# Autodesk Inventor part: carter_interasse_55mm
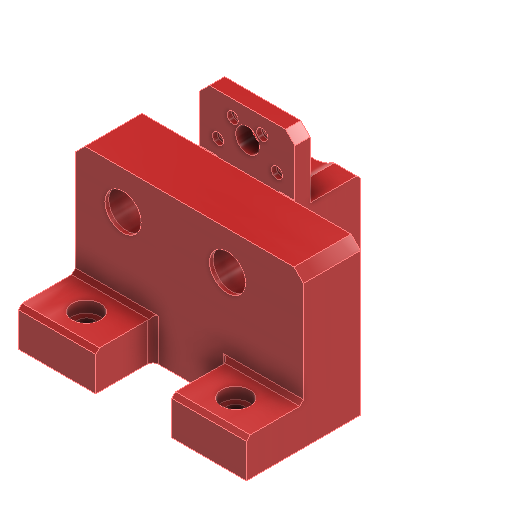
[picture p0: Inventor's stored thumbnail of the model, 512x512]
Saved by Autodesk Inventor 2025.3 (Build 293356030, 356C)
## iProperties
Created: 2026-09
Part Number: carter_interasse_55mm
Material: Plastica PET
Document SubType Name: Modeling
Designer: R5800u
Density: 1.541 g/cm^3
Appearance: Rosso
Author: R5800u
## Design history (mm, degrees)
sketch "Schizzo1"
  geometry: L1 (-75, 20)-(45, 20); L2 (45, 20)-(45, -40); L3 (45, -40)-(-75, -40); L4 (-75, -40)-(-75, 20); C1 r 11 at (5, 0); C2 r 11 at (-50, 0)
  constraints: 8 end point, 2 centre point, 2 parallel, 1 horizontal, 1 perpendicular
  dimensions: "d0" = 22 diameter of C1; "d1" = 22 diameter of C2; "d5" = 120 distance of L2.end L3.end; "d8" = 60 distance of L3.end L1.start; "d79" = 25 distance from line of L4 C2.centre; "d80" = 40 distance from line of L3 C2.centre; "d81" = 55 distance of C2.centre C1.centre
extrude "Estrusione1" new body sketch "Schizzo1" distance "d6" = 30; taper "d7" = 0 deg
sketch "Schizzo2"
  geometry: L1 (0, 0)-(120, 0) reference; L2 (0, 0)-(120, 0); L3 (120, 0)-(120, 60); L4 (120, 60)-(0, 60); L5 (0, 60)-(0, 0); 2 further points
  constraints: 8 end point, 2 parallel, 1 horizontal, 1 perpendicular
  dimensions: "d9" = 60 distance of L3.end L2.end
extrude "Estrusione2" join sketch "Schizzo2" distance "d10" = 20; taper "d11" = 0 deg
chamfer "Smusso2" distance "d15" = 2; stored, may be unused: second distance "d16" = 2, angle "d17" = 45 deg
sketch "Schizzo3"
  geometry: L1 (120, -30)-(0, -30) reference; L2 (99.309, -30)-(99.309, -60); L3 (120, -60)-(0, -60) reference; 2 further points
  constraints: 2 end point, 2 point on line, 1 midpoint, 1 vertical
hole "Foro1" sketch "Schizzo3" at (99.309, -45) diameter "d18" = 9; stored, may be unused: countersink angle "d22" = 90 deg, drill point angle "d24" = 118 deg; dims "d19" = 6, "d20" = 15, "d21" = 6, "d23" = 8
node "Piano di lavoro1"
mirror "Speculare1"
sketch "Schizzo4"
  geometry: C1 r 11 at (-50, 0) reference; C2 r 11 at (5, 0) reference; C3 r 9.5 at (-50, 0); C4 r 9.5 at (5, 0); 1 further point
  constraints: 2 centre point
  dimensions: "d25" = 1.5 radial gap between concentric circles of C1 C3; "d26" = 1.5 radial gap between concentric circles of C2 C4
extrude "Estrusione3" join sketch "Schizzo4" distance "d27" = 2; taper "d28" = 0 deg
sketch "Schizzo5"
  geometry: L1 (-5, 0)-(75, 0); L2 (75, 20)-(75, -60) reference; L3 (25, 0)-(25, -60); L4 (75, -60)-(-45, -60) reference; L5 (25, -20)-(75, -20); C1 r 18.5 at (50, -7) reference; C2 r 9.5 at (-5, 0) reference; 4 further points
  constraints: 6 end point, 4 point on line, 1 horizontal, 1 midpoint, 1 perpendicular
  dimensions: "d29" = 50 distance between parallel lines of L2 L3
extrude "Estrusione4" join sketch "Schizzo5" distance "d30" = 70; taper "d31" = 0 deg
node "Piano di lavoro2"
sketch "Schizzo6"
  geometry: L1 (-25, -53)-(-25, -13) reference; L2 (-25, -13)-(25, -13); L3 (25, -13)-(25, 22); L4 (25, 22)-(-25, 22); L5 (-25, 22)-(-25, -13); C1 r 18.5 at (0, 0) reference; C2 r 1.6 at (-7.75, 13.423) reference; C3 r 1.6 at (7.75, 13.423) reference; C4 r 1.6 at (-15.5, 0) reference; C5 r 1.6 at (15.5, 0) reference; C6 r 6.25 at (0, 7) reference; 3 further points
  constraints: 8 end point, 2 parallel, 1 horizontal, 1 perpendicular
  dimensions: "d34" = 35 distance of L3.end L2.end
extrude "Estrusione5" join sketch "Schizzo6" distance "d32" = 8; taper "d33" = 0 deg
chamfer "Smusso3" distance "d35" = 5; stored, may be unused: second distance "d36" = 2, angle "d37" = 45 deg
chamfer "Smusso4" distance "d38" = 5; stored, may be unused: second distance "d39" = 2, angle "d40" = 45 deg
sketch "Schizzo7"
  geometry: C1 r 1.6 at (-7.75, 13.423) reference; C2 r 1.6 at (7.75, 13.423) reference; C3 r 1.6 at (-15.5, 0) reference; C4 r 1.6 at (15.5, 0) reference; 5 further points
  constraints: 4 coincident
hole "Foro2" sketch "Schizzo7" at (-7.75, 13.423), (7.75, 13.423), (-15.5, 0), (15.5, 0) diameter "d41" = 3.4; stored, may be unused: countersink angle "d45" = 90 deg, drill point angle "d47" = 118 deg; dims "d42" = 6, "d43" = 5.8, "d44" = 2.4, "d46" = 8
sketch "Schizzo8"
  geometry: L1 (50, 0)-(120, 0) reference; L2 (120, 0)-(120, 60) reference; L3 (120, 60)-(0, 60) reference; L4 (0, 60)-(0, -70) reference; L5 (50, -70)-(0, -70) reference; L6 (50, 0)-(50, -70) reference; L7 (0, 0)-(50, 0); L8 (0, -5)-(50, -5); L9 (5, -65)-(5, 55); L10 (5, 55)-(115, 55); L11 (115, 55)-(115, 5); L12 (115, 5)-(45, 5); L13 (45, 5)-(45, -65); L14 (45, -65)-(5, -65); C1 r 4.5 at (20.691, 45) reference; C2 r 4.5 at (99.309, 45) reference; 3 further points
  constraints: 16 end point, 1 horizontal, 1 parallel, 1 point on line, 5 other
  dimensions: "d48" = 5 distance between parallel lines of L7 L8; "d49" = 5 distance between parallel lines of L4 L9
extrude "Estrusione6" cut sketch "Schizzo8" distance "d50" = 30; taper "d51" = 0 deg
fillet "Raccordo1" dims "d52" = 20
chamfer "Smusso5" distance "d53" = 2; stored, may be unused: second distance "d54" = 2, angle "d55" = 45 deg
node "Piano di lavoro4"
sketch "Schizzo9"
  geometry: C1 r 12 at (-5, 0); C2 r 11 at (-5, 0) reference; 1 further point
  constraints: 1 centre point, 1 coincident
  dimensions: "d58" = 24 diameter of C1
extrude "Estrusione7" cut sketch "Schizzo9" distance "d59" = 1; taper "d60" = 0 deg
sketch "Schizzo10"
  geometry: C1 r 11 at (50, 0) reference; C2 r 11 at (50, 0) reference; C3 r 11.5 at (50, 0); 1 further point
  constraints: 1 centre point
  dimensions: "d61" = 0.5 radial gap between concentric circles of C1 C3
extrude "Estrusione8" cut sketch "Schizzo10" distance "d62" = 1; taper "d63" = 0 deg
chamfer "Smusso6" distance "d64" = 5; stored, may be unused: second distance "d65" = 2, angle "d66" = 45 deg
sketch "Schizzo11"
  geometry: 1 further point
sketch "Schizzo12"
  geometry: L1 (114, 6)-(6, 6); L2 (6, 6)-(6, 24); L3 (6, 24)-(114, 24); L4 (114, 24)-(114, 6); L5 (55, 0)-(120, 0) reference; L6 (120, 0)-(120, 60) reference; L7 (0, 60)-(0, -70) reference; 1 further point
  constraints: 8 end point, 2 parallel, 1 horizontal, 1 perpendicular
  dimensions: "d67" = 6 distance between parallel lines of L5 L1; "d68" = 18 distance of L3.end L1.start; "d69" = 6 distance between parallel lines of L6 L4; "d70" = 6 distance between parallel lines of L7 L2
extrude "Estrusione9" cut sketch "Schizzo12" distance "d71" = 40; taper "d72" = 0 deg
fillet "Raccordo2" dims "d73" = 9
sketch "Schizzo13"
  geometry: L1 (120, -60)-(0, -60) reference; L2 (120, -30)-(0, -30) reference; L3 (40.691, -60)-(80.691, -60); L4 (80.691, -60)-(80.691, -30); L5 (80.691, -30)-(40.691, -30); L6 (40.691, -30)-(40.691, -60); C1 r 4.5 at (20.691, -45) reference; 3 further points
  constraints: 8 end point, 2 parallel, 2 point on line, 1 horizontal, 1 perpendicular
  dimensions: "d74" = 40 distance between parallel lines of L4 L6; "d75" = 20 distance from line of C1.centre L6
extrude "Estrusione10" cut sketch "Schizzo13" stored distance "d76" = 120; taper "d77" = 0 deg
fillet "Raccordo3" dims "d78" = 3
node "Solido1"
node "Riferimento1"
node "Riferimento2"
node "Riferimento3"
node "Riferimento4"
node "Riferimento5"
node "Riferimento6"
node "Riferimento7"
node "Linea chiusa proiettata1"
node "Linea chiusa proiettata2"
other parameters: "d57" = -1
